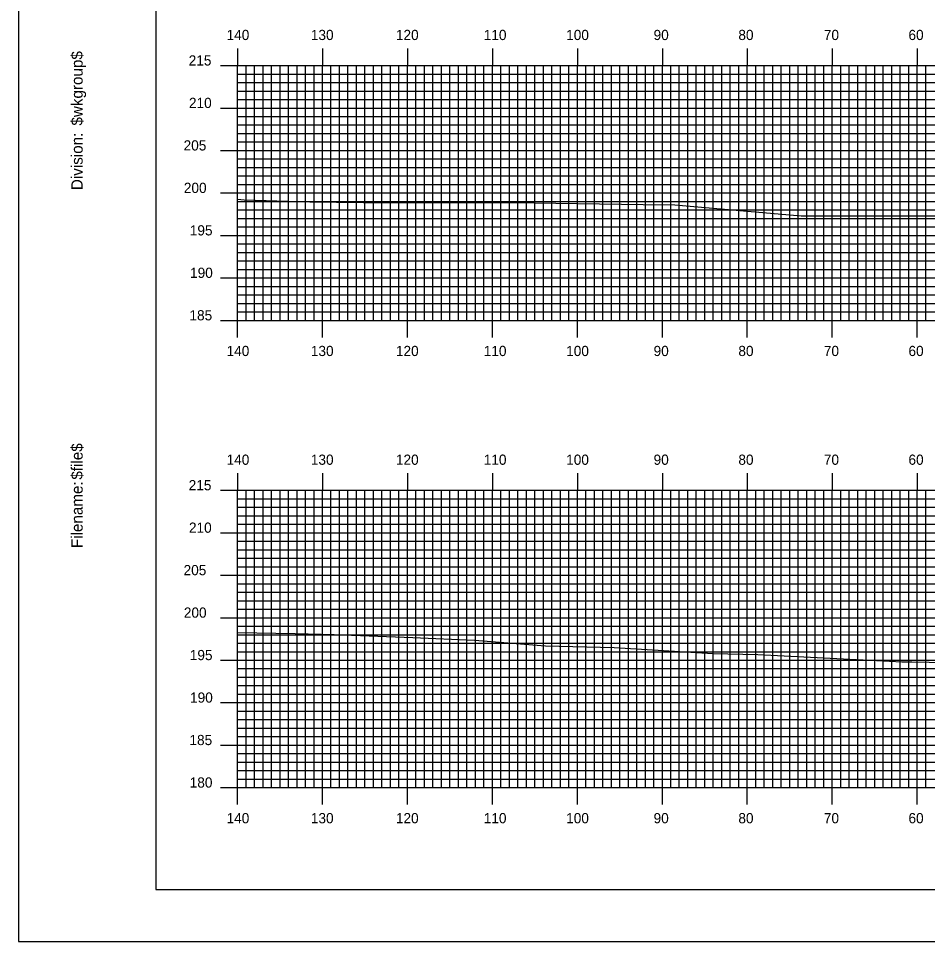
# Model space of a CAD drawing. Extents: x 1813735 to 1814078, y 442591 to 442811.
# Drawn here: x 1813734.7 to 1813841.7, y 442590.5 to 442699.2 of the extents above; entities that cross this region are included whole.
import ezdxf

# ---------------------------------------------------------------- set-up
doc = ezdxf.new("R2010")
doc.units = 0
for name, color, linetype in [('BORDER', 7, 'Continuous'), ('H_V ANNOTATION', 7, 'Continuous'), ('MAJOR', 7, 'Continuous'), ('MINOR', 7, 'Continuous'), ('PLOT BOUNDARY', 7, 'Continuous'), ('S_Roadway_Centerline', 7, 'Continuous')]:
    doc.layers.add(name, color=color, linetype=linetype)

msp = doc.modelspace()

# ---------------------------------------------------------------- linework, layer by layer
at = {"layer": 'BORDER'}
msp.add_lwpolyline([(1813750.88, 442596.67), (1814070.88, 442596.67), (1814070.88, 442806.67), (1813750.88, 442806.67)], close=True, dxfattribs=at)
at = {"layer": 'MAJOR'}
for p, q in [((1813760.48, 442695.67), (1813760.48, 442693.67)), ((1813770.48, 442695.67), (1813770.48, 442693.67)), ((1813780.48, 442695.67), (1813780.48, 442693.67)), ((1813790.48, 442695.67), (1813790.48, 442693.67)), ((1813800.48, 442695.67), (1813800.48, 442693.67)), ((1813810.48, 442695.67), (1813810.48, 442693.67)), ((1813820.48, 442695.67), (1813820.48, 442693.67)), ((1813830.48, 442695.67), (1813830.48, 442693.67)), ((1813840.48, 442695.67), (1813840.48, 442693.67)), ((1813758.48, 442693.67), (1813760.48, 442693.67)), ((1813760.48, 442693.67), (1814040.48, 442693.67)), ((1813760.48, 442663.67), (1813760.48, 442693.67)), ((1813760.48, 442663.67), (1813760.48, 442693.67)), ((1813760.48, 442693.67), (1814040.48, 442693.67)), ((1813770.48, 442663.67), (1813770.48, 442693.67)), ((1813780.48, 442663.67), (1813780.48, 442693.67)), ((1813790.48, 442663.67), (1813790.48, 442693.67)), ((1813800.48, 442663.67), (1813800.48, 442693.67)), ((1813810.48, 442663.67), (1813810.48, 442693.67)), ((1813820.48, 442663.67), (1813820.48, 442693.67)), ((1813830.48, 442663.67), (1813830.48, 442693.67)), ((1813840.48, 442663.67), (1813840.48, 442693.67)), ((1813758.48, 442688.67), (1813760.48, 442688.67)), ((1813760.48, 442688.67), (1814040.48, 442688.67)), ((1813758.48, 442683.67), (1813760.48, 442683.67)), ((1813760.48, 442683.67), (1814040.48, 442683.67)), ((1813758.48, 442678.67), (1813760.48, 442678.67)), ((1813760.48, 442678.67), (1814040.48, 442678.67)), ((1813758.48, 442673.67), (1813760.48, 442673.67)), ((1813760.48, 442673.67), (1814040.48, 442673.67)), ((1813758.48, 442668.67), (1813760.48, 442668.67)), ((1813760.48, 442668.67), (1814040.48, 442668.67)), ((1813758.48, 442663.67), (1813760.48, 442663.67)), ((1813760.48, 442663.67), (1814040.48, 442663.67)), ((1813760.48, 442663.67), (1814040.48, 442663.67)), ((1813760.48, 442661.66), (1813760.48, 442663.67)), ((1813770.48, 442661.66), (1813770.48, 442663.67)), ((1813780.48, 442661.66), (1813780.48, 442663.67)), ((1813790.48, 442661.66), (1813790.48, 442663.67)), ((1813800.48, 442661.66), (1813800.48, 442663.67)), ((1813810.48, 442661.66), (1813810.48, 442663.67)), ((1813820.48, 442661.66), (1813820.48, 442663.67)), ((1813830.48, 442661.66), (1813830.48, 442663.67)), ((1813840.48, 442661.66), (1813840.48, 442663.67)), ((1813760.48, 442645.67), (1813760.48, 442643.67)), ((1813770.48, 442645.67), (1813770.48, 442643.67)), ((1813780.48, 442645.67), (1813780.48, 442643.67)), ((1813790.48, 442645.67), (1813790.48, 442643.67)), ((1813800.48, 442645.67), (1813800.48, 442643.67)), ((1813810.48, 442645.67), (1813810.48, 442643.67)), ((1813820.48, 442645.67), (1813820.48, 442643.67)), ((1813830.48, 442645.67), (1813830.48, 442643.67)), ((1813840.48, 442645.67), (1813840.48, 442643.67)), ((1813758.48, 442643.67), (1813760.48, 442643.67)), ((1813760.48, 442643.67), (1814040.48, 442643.67)), ((1813760.48, 442608.67), (1813760.48, 442643.67)), ((1813760.48, 442608.67), (1813760.48, 442643.67)), ((1813760.48, 442643.67), (1814040.48, 442643.67)), ((1813770.48, 442608.67), (1813770.48, 442643.67)), ((1813780.48, 442608.67), (1813780.48, 442643.67)), ((1813790.48, 442608.67), (1813790.48, 442643.67)), ((1813800.48, 442608.67), (1813800.48, 442643.67)), ((1813810.48, 442608.67), (1813810.48, 442643.67)), ((1813820.48, 442608.67), (1813820.48, 442643.67)), ((1813830.48, 442608.67), (1813830.48, 442643.67)), ((1813840.48, 442608.67), (1813840.48, 442643.67)), ((1813758.48, 442638.67), (1813760.48, 442638.67)), ((1813760.48, 442638.67), (1814040.48, 442638.67)), ((1813758.48, 442633.67), (1813760.48, 442633.67)), ((1813760.48, 442633.67), (1814040.48, 442633.67)), ((1813758.48, 442628.67), (1813760.48, 442628.67)), ((1813760.48, 442628.67), (1814040.48, 442628.67)), ((1813758.48, 442623.67), (1813760.48, 442623.67)), ((1813760.48, 442623.67), (1814040.48, 442623.67)), ((1813758.48, 442618.67), (1813760.48, 442618.67)), ((1813760.48, 442618.67), (1814040.48, 442618.67)), ((1813758.48, 442613.67), (1813760.48, 442613.67)), ((1813760.48, 442613.67), (1814040.48, 442613.67)), ((1813758.48, 442608.67), (1813760.48, 442608.67)), ((1813760.48, 442608.67), (1814040.48, 442608.67)), ((1813760.48, 442608.67), (1814040.48, 442608.67)), ((1813760.48, 442606.66), (1813760.48, 442608.67)), ((1813770.48, 442606.66), (1813770.48, 442608.67)), ((1813780.48, 442606.66), (1813780.48, 442608.67)), ((1813790.48, 442606.66), (1813790.48, 442608.67)), ((1813800.48, 442606.66), (1813800.48, 442608.67)), ((1813810.48, 442606.66), (1813810.48, 442608.67)), ((1813820.48, 442606.66), (1813820.48, 442608.67)), ((1813830.48, 442606.66), (1813830.48, 442608.67)), ((1813840.48, 442606.66), (1813840.48, 442608.67))]:
    msp.add_line(p, q, dxfattribs=at)
at = {"layer": 'MINOR'}
for p, q in [((1813761.48, 442663.67), (1813761.48, 442693.67)), ((1813762.48, 442663.67), (1813762.48, 442693.67)), ((1813763.48, 442663.67), (1813763.48, 442693.67)), ((1813764.48, 442663.67), (1813764.48, 442693.67)), ((1813765.48, 442663.67), (1813765.48, 442693.67)), ((1813766.48, 442663.67), (1813766.48, 442693.67)), ((1813767.48, 442663.67), (1813767.48, 442693.67)), ((1813768.48, 442663.67), (1813768.48, 442693.67)), ((1813769.48, 442663.67), (1813769.48, 442693.67)), ((1813771.48, 442663.67), (1813771.48, 442693.67)), ((1813772.48, 442663.67), (1813772.48, 442693.67)), ((1813773.48, 442663.67), (1813773.48, 442693.67)), ((1813774.48, 442663.67), (1813774.48, 442693.67)), ((1813775.48, 442663.67), (1813775.48, 442693.67)), ((1813776.48, 442663.67), (1813776.48, 442693.67)), ((1813777.48, 442663.67), (1813777.48, 442693.67)), ((1813778.48, 442663.67), (1813778.48, 442693.67)), ((1813779.48, 442663.67), (1813779.48, 442693.67)), ((1813781.48, 442663.67), (1813781.48, 442693.67)), ((1813782.48, 442663.67), (1813782.48, 442693.67)), ((1813783.48, 442663.67), (1813783.48, 442693.67)), ((1813784.48, 442663.67), (1813784.48, 442693.67)), ((1813785.48, 442663.67), (1813785.48, 442693.67)), ((1813786.48, 442663.67), (1813786.48, 442693.67)), ((1813787.48, 442663.67), (1813787.48, 442693.67)), ((1813788.48, 442663.67), (1813788.48, 442693.67)), ((1813789.48, 442663.67), (1813789.48, 442693.67)), ((1813791.48, 442663.67), (1813791.48, 442693.67)), ((1813792.48, 442663.67), (1813792.48, 442693.67)), ((1813793.48, 442663.67), (1813793.48, 442693.67)), ((1813794.48, 442663.67), (1813794.48, 442693.67)), ((1813795.48, 442663.67), (1813795.48, 442693.67)), ((1813796.48, 442663.67), (1813796.48, 442693.67)), ((1813797.48, 442663.67), (1813797.48, 442693.67)), ((1813798.48, 442663.67), (1813798.48, 442693.67)), ((1813799.48, 442663.67), (1813799.48, 442693.67)), ((1813801.48, 442663.67), (1813801.48, 442693.67)), ((1813802.48, 442663.67), (1813802.48, 442693.67)), ((1813803.48, 442663.67), (1813803.48, 442693.67)), ((1813804.48, 442663.67), (1813804.48, 442693.67)), ((1813805.48, 442663.67), (1813805.48, 442693.67)), ((1813806.48, 442663.67), (1813806.48, 442693.67)), ((1813807.48, 442663.67), (1813807.48, 442693.67)), ((1813808.48, 442663.67), (1813808.48, 442693.67)), ((1813809.48, 442663.67), (1813809.48, 442693.67)), ((1813811.48, 442663.67), (1813811.48, 442693.67)), ((1813812.48, 442663.67), (1813812.48, 442693.67)), ((1813813.48, 442663.67), (1813813.48, 442693.67)), ((1813814.48, 442663.67), (1813814.48, 442693.67)), ((1813815.48, 442663.67), (1813815.48, 442693.67)), ((1813816.48, 442663.67), (1813816.48, 442693.67)), ((1813817.48, 442663.67), (1813817.48, 442693.67)), ((1813818.48, 442663.67), (1813818.48, 442693.67)), ((1813819.48, 442663.67), (1813819.48, 442693.67)), ((1813821.48, 442663.67), (1813821.48, 442693.67)), ((1813822.48, 442663.67), (1813822.48, 442693.67)), ((1813823.48, 442663.67), (1813823.48, 442693.67)), ((1813824.48, 442663.67), (1813824.48, 442693.67)), ((1813825.48, 442663.67), (1813825.48, 442693.67)), ((1813826.48, 442663.67), (1813826.48, 442693.67)), ((1813827.48, 442663.67), (1813827.48, 442693.67)), ((1813828.48, 442663.67), (1813828.48, 442693.67)), ((1813829.48, 442663.67), (1813829.48, 442693.67)), ((1813831.48, 442663.67), (1813831.48, 442693.67)), ((1813832.48, 442663.67), (1813832.48, 442693.67)), ((1813833.48, 442663.67), (1813833.48, 442693.67)), ((1813834.48, 442663.67), (1813834.48, 442693.67)), ((1813835.48, 442663.67), (1813835.48, 442693.67)), ((1813836.48, 442663.67), (1813836.48, 442693.67)), ((1813837.48, 442663.67), (1813837.48, 442693.67)), ((1813838.48, 442663.67), (1813838.48, 442693.67)), ((1813839.48, 442663.67), (1813839.48, 442693.67)), ((1813841.48, 442663.67), (1813841.48, 442693.67)), ((1813760.48, 442692.67), (1814040.48, 442692.67)), ((1813760.48, 442692.67), (1813762.49, 442692.67)), ((1813760.48, 442691.67), (1814040.48, 442691.67)), ((1813760.48, 442691.67), (1813762.49, 442691.67)), ((1813760.48, 442690.67), (1814040.48, 442690.67)), ((1813760.48, 442690.67), (1813762.49, 442690.67)), ((1813760.48, 442689.67), (1814040.48, 442689.67)), ((1813760.48, 442689.67), (1813762.49, 442689.67)), ((1813760.48, 442687.67), (1814040.48, 442687.67)), ((1813760.48, 442687.67), (1813762.49, 442687.67)), ((1813760.48, 442686.67), (1814040.48, 442686.67)), ((1813760.48, 442686.67), (1813762.49, 442686.67)), ((1813760.48, 442685.67), (1814040.48, 442685.67)), ((1813760.48, 442685.67), (1813762.49, 442685.67)), ((1813760.48, 442684.67), (1814040.48, 442684.67)), ((1813760.48, 442684.67), (1813762.49, 442684.67)), ((1813760.48, 442682.67), (1814040.48, 442682.67)), ((1813760.48, 442682.67), (1813762.49, 442682.67)), ((1813760.48, 442681.67), (1814040.48, 442681.67)), ((1813760.48, 442681.67), (1813762.49, 442681.67)), ((1813760.48, 442680.67), (1814040.48, 442680.67)), ((1813760.48, 442680.67), (1813762.49, 442680.67)), ((1813760.48, 442679.67), (1814040.48, 442679.67)), ((1813760.48, 442679.67), (1813762.49, 442679.67)), ((1813760.48, 442677.67), (1814040.48, 442677.67)), ((1813760.48, 442677.67), (1813762.49, 442677.67)), ((1813760.48, 442676.67), (1814040.48, 442676.67)), ((1813760.48, 442676.67), (1813762.49, 442676.67)), ((1813760.48, 442675.67), (1814040.48, 442675.67)), ((1813760.48, 442675.67), (1813762.49, 442675.67)), ((1813760.48, 442674.67), (1814040.48, 442674.67)), ((1813760.48, 442674.67), (1813762.49, 442674.67)), ((1813760.48, 442672.67), (1814040.48, 442672.67)), ((1813760.48, 442672.67), (1813762.49, 442672.67)), ((1813760.48, 442671.67), (1814040.48, 442671.67)), ((1813760.48, 442671.67), (1813762.49, 442671.67)), ((1813760.48, 442670.67), (1814040.48, 442670.67)), ((1813760.48, 442670.67), (1813762.49, 442670.67)), ((1813760.48, 442669.67), (1814040.48, 442669.67)), ((1813760.48, 442669.67), (1813762.49, 442669.67)), ((1813760.48, 442667.67), (1814040.48, 442667.67)), ((1813760.48, 442667.67), (1813762.49, 442667.67)), ((1813760.48, 442666.67), (1814040.48, 442666.67)), ((1813760.48, 442666.67), (1813762.49, 442666.67)), ((1813760.48, 442665.67), (1814040.48, 442665.67)), ((1813760.48, 442665.67), (1813762.49, 442665.67)), ((1813760.48, 442664.67), (1814040.48, 442664.67)), ((1813760.48, 442664.67), (1813762.49, 442664.67)), ((1813761.48, 442608.67), (1813761.48, 442643.67)), ((1813762.48, 442608.67), (1813762.48, 442643.67)), ((1813763.48, 442608.67), (1813763.48, 442643.67)), ((1813764.48, 442608.67), (1813764.48, 442643.67)), ((1813765.48, 442608.67), (1813765.48, 442643.67)), ((1813766.48, 442608.67), (1813766.48, 442643.67)), ((1813767.48, 442608.67), (1813767.48, 442643.67)), ((1813768.48, 442608.67), (1813768.48, 442643.67)), ((1813769.48, 442608.67), (1813769.48, 442643.67)), ((1813771.48, 442608.67), (1813771.48, 442643.67)), ((1813772.48, 442608.67), (1813772.48, 442643.67)), ((1813773.48, 442608.67), (1813773.48, 442643.67)), ((1813774.48, 442608.67), (1813774.48, 442643.67)), ((1813775.48, 442608.67), (1813775.48, 442643.67)), ((1813776.48, 442608.67), (1813776.48, 442643.67)), ((1813777.48, 442608.67), (1813777.48, 442643.67)), ((1813778.48, 442608.67), (1813778.48, 442643.67)), ((1813779.48, 442608.67), (1813779.48, 442643.67)), ((1813781.48, 442608.67), (1813781.48, 442643.67)), ((1813782.48, 442608.67), (1813782.48, 442643.67)), ((1813783.48, 442608.67), (1813783.48, 442643.67)), ((1813784.48, 442608.67), (1813784.48, 442643.67)), ((1813785.48, 442608.67), (1813785.48, 442643.67)), ((1813786.48, 442608.67), (1813786.48, 442643.67)), ((1813787.48, 442608.67), (1813787.48, 442643.67)), ((1813788.48, 442608.67), (1813788.48, 442643.67)), ((1813789.48, 442608.67), (1813789.48, 442643.67)), ((1813791.48, 442608.67), (1813791.48, 442643.67)), ((1813792.48, 442608.67), (1813792.48, 442643.67)), ((1813793.48, 442608.67), (1813793.48, 442643.67)), ((1813794.48, 442608.67), (1813794.48, 442643.67)), ((1813795.48, 442608.67), (1813795.48, 442643.67)), ((1813796.48, 442608.67), (1813796.48, 442643.67)), ((1813797.48, 442608.67), (1813797.48, 442643.67)), ((1813798.48, 442608.67), (1813798.48, 442643.67)), ((1813799.48, 442608.67), (1813799.48, 442643.67)), ((1813801.48, 442608.67), (1813801.48, 442643.67)), ((1813802.48, 442608.67), (1813802.48, 442643.67)), ((1813803.48, 442608.67), (1813803.48, 442643.67)), ((1813804.48, 442608.67), (1813804.48, 442643.67)), ((1813805.48, 442608.67), (1813805.48, 442643.67)), ((1813806.48, 442608.67), (1813806.48, 442643.67)), ((1813807.48, 442608.67), (1813807.48, 442643.67)), ((1813808.48, 442608.67), (1813808.48, 442643.67)), ((1813809.48, 442608.67), (1813809.48, 442643.67)), ((1813811.48, 442608.67), (1813811.48, 442643.67)), ((1813812.48, 442608.67), (1813812.48, 442643.67)), ((1813813.48, 442608.67), (1813813.48, 442643.67)), ((1813814.48, 442608.67), (1813814.48, 442643.67)), ((1813815.48, 442608.67), (1813815.48, 442643.67)), ((1813816.48, 442608.67), (1813816.48, 442643.67)), ((1813817.48, 442608.67), (1813817.48, 442643.67)), ((1813818.48, 442608.67), (1813818.48, 442643.67)), ((1813819.48, 442608.67), (1813819.48, 442643.67)), ((1813821.48, 442608.67), (1813821.48, 442643.67)), ((1813822.48, 442608.67), (1813822.48, 442643.67)), ((1813823.48, 442608.67), (1813823.48, 442643.67)), ((1813824.48, 442608.67), (1813824.48, 442643.67)), ((1813825.48, 442608.67), (1813825.48, 442643.67)), ((1813826.48, 442608.67), (1813826.48, 442643.67)), ((1813827.48, 442608.67), (1813827.48, 442643.67)), ((1813828.48, 442608.67), (1813828.48, 442643.67)), ((1813829.48, 442608.67), (1813829.48, 442643.67)), ((1813831.48, 442608.67), (1813831.48, 442643.67)), ((1813832.48, 442608.67), (1813832.48, 442643.67)), ((1813833.48, 442608.67), (1813833.48, 442643.67)), ((1813834.48, 442608.67), (1813834.48, 442643.67)), ((1813835.48, 442608.67), (1813835.48, 442643.67)), ((1813836.48, 442608.67), (1813836.48, 442643.67)), ((1813837.48, 442608.67), (1813837.48, 442643.67)), ((1813838.48, 442608.67), (1813838.48, 442643.67)), ((1813839.48, 442608.67), (1813839.48, 442643.67)), ((1813841.48, 442608.67), (1813841.48, 442643.67)), ((1813760.48, 442642.67), (1814040.48, 442642.67)), ((1813760.48, 442642.67), (1813762.49, 442642.67)), ((1813760.48, 442641.67), (1814040.48, 442641.67)), ((1813760.48, 442641.67), (1813762.49, 442641.67)), ((1813760.48, 442640.67), (1814040.48, 442640.67)), ((1813760.48, 442640.67), (1813762.49, 442640.67)), ((1813760.48, 442639.67), (1814040.48, 442639.67)), ((1813760.48, 442639.67), (1813762.49, 442639.67)), ((1813760.48, 442637.67), (1814040.48, 442637.67)), ((1813760.48, 442637.67), (1813762.49, 442637.67)), ((1813760.48, 442636.67), (1814040.48, 442636.67)), ((1813760.48, 442636.67), (1813762.49, 442636.67)), ((1813760.48, 442635.67), (1814040.48, 442635.67)), ((1813760.48, 442635.67), (1813762.49, 442635.67)), ((1813760.48, 442634.67), (1814040.48, 442634.67)), ((1813760.48, 442634.67), (1813762.49, 442634.67)), ((1813760.48, 442632.67), (1814040.48, 442632.67)), ((1813760.48, 442632.67), (1813762.49, 442632.67)), ((1813760.48, 442631.67), (1814040.48, 442631.67)), ((1813760.48, 442631.67), (1813762.49, 442631.67)), ((1813760.48, 442630.67), (1814040.48, 442630.67)), ((1813760.48, 442630.67), (1813762.49, 442630.67)), ((1813760.48, 442629.67), (1814040.48, 442629.67)), ((1813760.48, 442629.67), (1813762.49, 442629.67)), ((1813760.48, 442627.67), (1814040.48, 442627.67)), ((1813760.48, 442627.67), (1813762.49, 442627.67)), ((1813760.48, 442626.67), (1814040.48, 442626.67)), ((1813760.48, 442626.67), (1813762.49, 442626.67)), ((1813760.48, 442625.67), (1814040.48, 442625.67)), ((1813760.48, 442625.67), (1813762.49, 442625.67)), ((1813760.48, 442624.67), (1814040.48, 442624.67)), ((1813760.48, 442624.67), (1813762.49, 442624.67)), ((1813760.48, 442622.67), (1814040.48, 442622.67)), ((1813760.48, 442622.67), (1813762.49, 442622.67)), ((1813760.48, 442621.67), (1814040.48, 442621.67)), ((1813760.48, 442621.67), (1813762.49, 442621.67)), ((1813760.48, 442620.67), (1814040.48, 442620.67)), ((1813760.48, 442620.67), (1813762.49, 442620.67)), ((1813760.48, 442619.67), (1814040.48, 442619.67)), ((1813760.48, 442619.67), (1813762.49, 442619.67)), ((1813760.48, 442617.67), (1814040.48, 442617.67)), ((1813760.48, 442617.67), (1813762.49, 442617.67)), ((1813760.48, 442616.67), (1814040.48, 442616.67)), ((1813760.48, 442616.67), (1813762.49, 442616.67)), ((1813760.48, 442615.67), (1814040.48, 442615.67)), ((1813760.48, 442615.67), (1813762.49, 442615.67)), ((1813760.48, 442614.67), (1814040.48, 442614.67)), ((1813760.48, 442614.67), (1813762.49, 442614.67)), ((1813760.48, 442612.67), (1814040.48, 442612.67)), ((1813760.48, 442612.67), (1813762.49, 442612.67)), ((1813760.48, 442611.67), (1814040.48, 442611.67)), ((1813760.48, 442611.67), (1813762.49, 442611.67)), ((1813760.48, 442610.67), (1814040.48, 442610.67)), ((1813760.48, 442610.67), (1813762.49, 442610.67)), ((1813760.48, 442609.67), (1814040.48, 442609.67)), ((1813760.48, 442609.67), (1813762.49, 442609.67))]:
    msp.add_line(p, q, dxfattribs=at)
at = {"layer": 'PLOT BOUNDARY'}
msp.add_lwpolyline([(1813734.69, 442590.55), (1814074.69, 442590.55), (1814074.69, 442810.55), (1813734.69, 442810.55)], close=True, dxfattribs=at)
at = {"layer": 'S_Roadway_Centerline'}
for points in [[(1813760.48, 442677.93), (1813761.26, 442677.87), (1813769, 442677.63), (1813778.45, 442677.5), (1813789.75, 442677.53), (1813795.38, 442677.52), (1813808.22, 442677.32), (1813811.97, 442677.27), (1813826.36, 442676.02), (1813826.82, 442675.98), (1813834.67, 442675.97), (1813844.5, 442675.98)], [(1813760.48, 442626.91), (1813767.28, 442626.79), (1813771.85, 442626.69), (1813781.12, 442626.34), (1813788.38, 442626.04), (1813796.73, 442625.35), (1813804.81, 442625.16), (1813816.41, 442624.47), (1813821.73, 442624.32), (1813837.2, 442623.54), (1813838.68, 442623.48), (1813839.85, 442623.47), (1813848.02, 442623.3)]]:
    msp.add_lwpolyline(points, dxfattribs=at)

# ---------------------------------------------------------------- texts
at = {"layer": 'BORDER'}
for s, p in [('$wkgroup$', (1813742.25, 442686.6)), ('Division:', (1813742.25, 442679)), ('$file$', (1813742.25, 442644.92)), ('Filename:', (1813742.25, 442636.86))]:
    msp.add_text(s, height=1.339, rotation=90, dxfattribs=at).set_placement(p)
at = {"layer": 'H_V ANNOTATION'}
for s, p in [('140', (1813759.19, 442696.67)), ('130', (1813769.11, 442696.67)), ('120', (1813779.12, 442696.67)), ('110', (1813789.46, 442696.67)), ('100', (1813799.16, 442696.67)), ('90', (1813809.45, 442696.67)), ('80', (1813819.43, 442696.67)), ('70', (1813829.49, 442696.67)), ('60', (1813839.45, 442696.67)), ('215', (1813754.73, 442693.67)), ('210', (1813754.76, 442688.67)), ('205', (1813754.13, 442683.67)), ('200', (1813754.16, 442678.67)), ('195', (1813754.86, 442673.67)), ('190', (1813754.89, 442668.67)), ('185', (1813754.82, 442663.67)), ('140', (1813759.19, 442659.47)), ('130', (1813769.11, 442659.47)), ('120', (1813779.12, 442659.47)), ('110', (1813789.46, 442659.47)), ('100', (1813799.16, 442659.47)), ('90', (1813809.45, 442659.47)), ('80', (1813819.43, 442659.47)), ('70', (1813829.49, 442659.47)), ('60', (1813839.45, 442659.47)), ('140', (1813759.19, 442646.67)), ('130', (1813769.11, 442646.67)), ('120', (1813779.12, 442646.67)), ('110', (1813789.46, 442646.67)), ('100', (1813799.16, 442646.67)), ('90', (1813809.45, 442646.67)), ('80', (1813819.43, 442646.67)), ('70', (1813829.49, 442646.67)), ('60', (1813839.45, 442646.67)), ('215', (1813754.73, 442643.67)), ('210', (1813754.76, 442638.67)), ('205', (1813754.13, 442633.67)), ('200', (1813754.16, 442628.67)), ('195', (1813754.86, 442623.67)), ('190', (1813754.89, 442618.67)), ('185', (1813754.82, 442613.67)), ('180', (1813754.85, 442608.67)), ('140', (1813759.19, 442604.47)), ('130', (1813769.11, 442604.47)), ('120', (1813779.12, 442604.47)), ('110', (1813789.46, 442604.47)), ('100', (1813799.16, 442604.47)), ('90', (1813809.45, 442604.47)), ('80', (1813819.43, 442604.47)), ('70', (1813829.49, 442604.47)), ('60', (1813839.45, 442604.47))]:
    msp.add_text(s, height=1.2, dxfattribs=at).set_placement(p)
at = {"layer": 'MAJOR'}
for p in [(1813760.47, 442663.67), (1813760.47, 442608.67)]:
    msp.add_text('-', height=0.012, dxfattribs=at).set_placement(p)

doc.saveas('drawing.dxf')
